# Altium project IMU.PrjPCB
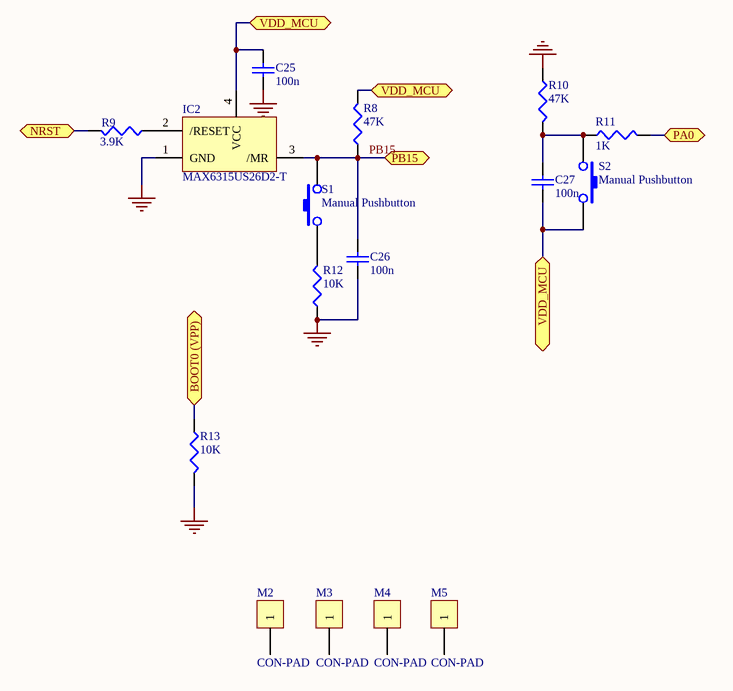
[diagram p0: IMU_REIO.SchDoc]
4 sheets, 58 parts. Net scope: flat (ports and power ports of the same name join across sheets).
Board file: IMU(G).PcbDoc
Sheets:
  IMU_REIO.SchDoc
  IMU_Blue.SchDoc
  CPU_STM32F4.SchDoc
  IMU_POW.SchDoc

## Sheet IMU_REIO.SchDoc
size A4

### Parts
C25  100n  [0603]
C26  100n  [0603]
C27  100n  [0603]
IC2  MAX6315US26D2-T  [TO-253]
M2  CON-PAD  [BAD_MARK]
M3  CON-PAD  [BAD_MARK]
M4  CON-PAD  [BAD_MARK]
M5  CON-PAD  [BAD_MARK]
R8  47K  [0603]
R9  3.9K  [0603]
R10  47K  [0603]
R11  1K  [0603]
R12  10K  [0603]
R13  10K  [0603]
S1  Manual Pushbutton  [KEY-6*4]
S2  Manual Pushbutton  [KEY-6*4]

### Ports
BOOT0 (VPP), NRST, PA0, PB15, VDD_MCU

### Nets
GND: C25.2 C26.2 IC2.1(GND) R10.1 R12.1 R13.2
VBAT: C25.1 C27.2 IC2.4(VCC) R8.2 S2.2 ; port VDD_MCU
BOOT0 (VPP): R13.1 ; port BOOT0 (VPP)
NRST: R9.2 ; port NRST
PA0: R11.2 ; port PA0
PB15: C26.1 IC2.3(/MR) R8.1 S1.2 ; port PB15
NetC27_1: C27.1 R10.2 R11.1 S2.1
NetIC2_2: IC2.2(/RESET) R9.1
NetR12_2: R12.2 S1.1

Not connected (* = marked no-connect by the designer): M2 1; M3 1; M4 1; M5 1

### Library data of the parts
C25-C27 = Cap: TANTAMOUNT? 595D Vishay Sprague,50V,22.5mOhm
IC2 = MAX 6468: MAX 6468XS16D3 Reset and Supervisory Circuit
R8-R13 = Res3: Resistor
S1 S2 = 微动开关

## Sheet IMU_Blue.SchDoc
size A3
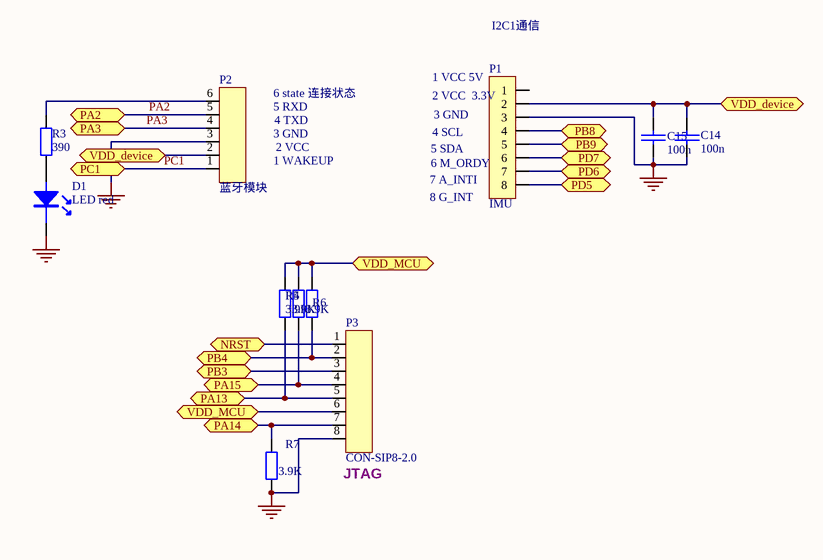
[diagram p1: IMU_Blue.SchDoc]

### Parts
C14  100n  [0603]
C15  100n  [0603]
D1  LED red  [D0805]
P1  IMU  [GY-85]
P2  蓝牙模块  [HC-06(35.7*15.2MM)]
P3  CON-SIP8-2.0  [PLUG1.27-8P]
R3  390  [0603]
R4  3.9K  [0603]
R5  3.9K  [0603]
R6  3.9K  [0603]
R7  3.9K  [0603]

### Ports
NRST, PA2, PA3, PA13, PA14, PA15, PB3, PB4, PB8, PB9, PC1, PD5, PD6, PD7, VDD_device, VDD_MCU

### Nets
GND: C14.1 C15.1 D1.K P1.3 P2.3 P3.8 R7.1
VBAT: P3.6 R4.2 R5.2 R6.2 ; port VDD_MCU
VDD_device: C14.2 C15.2 P1.2 P2.2 ; port VDD_device
NRST: P3.1 ; port NRST
PA2: P2.5 ; port PA2
PA3: P2.4 ; port PA3
PA13: P3.5 R4.1 ; port PA13
PA14: P3.7 R7.2 ; port PA14
PA15: P3.4 R5.1 ; port PA15
PB3: P3.3 ; port PB3
PB4: P3.2 R6.1 ; port PB4
PB8: P1.4 ; port PB8
PB9: P1.5 ; port PB9
PC1: P2.1 ; port PC1
PD5: P1.8 ; port PD5
PD6: P1.7 ; port PD6
PD7: P1.6 ; port PD7
NetD1_A: D1.A R3.1
NetP2_6: P2.6 R3.2

Not connected (* = marked no-connect by the designer): P1 1

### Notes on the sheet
- I2C1通信
- 6 state 连接状态
- 5 RXD
- 3 GND
- 4 TXD
- (near P1) 4 SCL
- (near P1) 1 VCC 5V
- (near P1) 2 VCC  3.3V
- (near P1) 3 GND
- 1 WAKEUP
- 2 VCC
- (near P1) 7 A_INTI
- (near P1) 8 G_INT
- (near P1) 6 M_ORDY
- 5 SDA
- (near P3) JTAG

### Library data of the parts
C14 C15 = C-SMD
D1 = diode-LED: LED
P1 = CON8-2.54: (栅)围栏式立(卧)8PIN
P2 = CON-SIP6-2.54: 单排针6PIN
P3 = CON-SIP8-2.0: 单排针8PIN
R3 = R-0603: 0603(SMD); 功率: 1/10w
R4-R7 = R-0805: 0805(SMD); 功率: 1/8w

## Sheet CPU_STM32F4.SchDoc
size A2
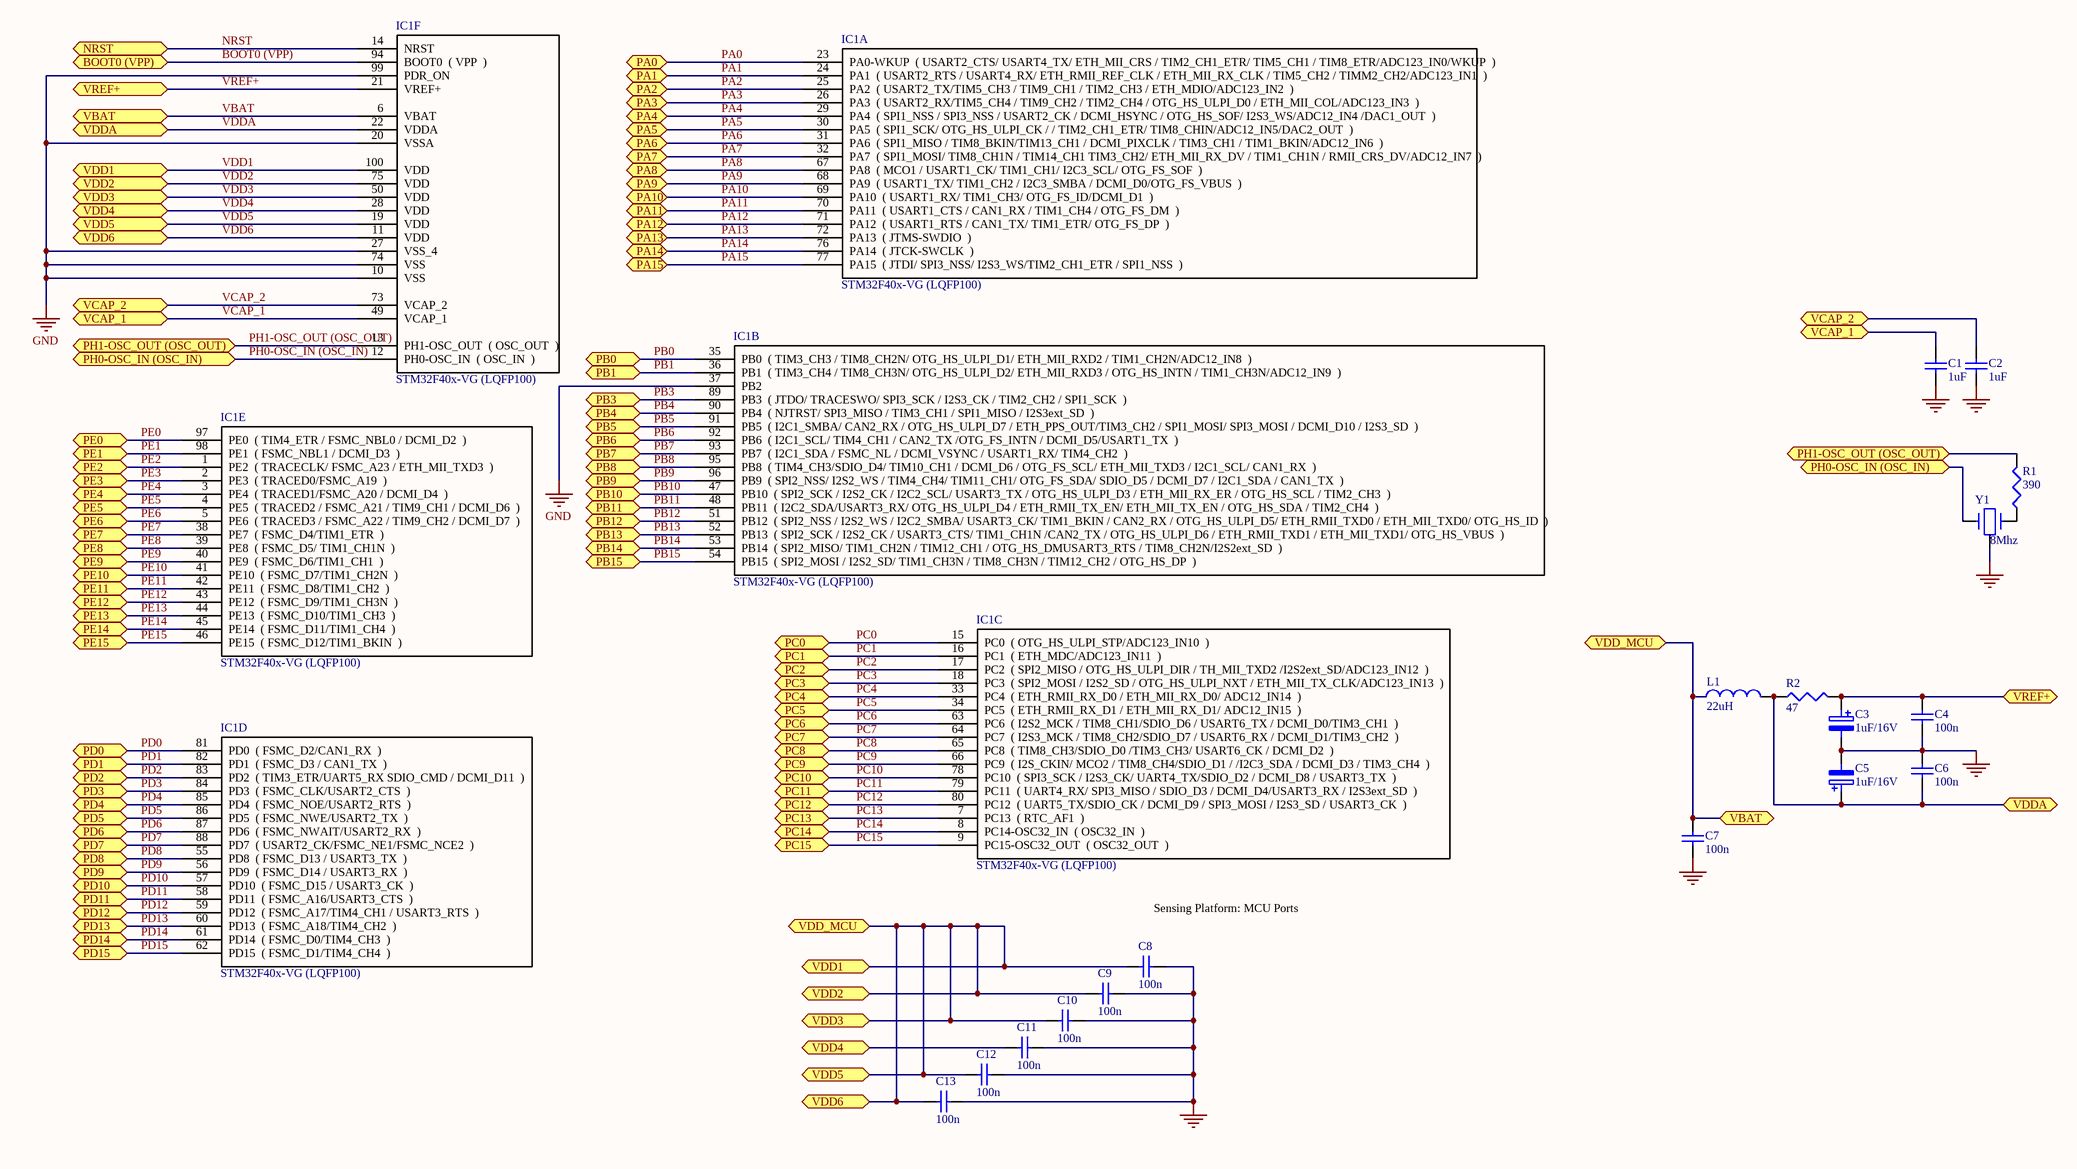
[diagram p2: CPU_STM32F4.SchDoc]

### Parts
C1  1uF  [0603]
C2  1uF  [0603]
C3  1uF/16V  [C-0805]
C4  100n  [0603]
C5  1uF/16V  [C-0805]
C6  100n  [0603]
C7  100n  [0603]
C8  100n  [0603]
C9  100n  [0603]
C10  100n  [0603]
C11  100n  [0603]
C12  100n  [0603]
C13  100n  [0603]
IC1  STM32F40x-VG (LQFP100)  [LQFP100 (14*14)]  (parts A,B,C,D,E,F of 6)
L1  22uH  [0603]
R1  390  [0603]
R2  47  [0603]
Y1  8Mhz  [XT-3.2*1.5]

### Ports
BOOT0 (VPP), NRST, PA0, PA1, PA2, PA3, PA4, PA5, PA6, PA7, PA8, PA9, PA10, PA11, PA12, PA13, PA14, PA15, PB0, PB1, PB3, PB4, PB5, PB6, PB7, PB8, PB9, PB10, PB11, PB12, PB13, PB14, PB15, PC0, PC1, PC2, PC3, PC4, PC5, PC6, PC7, PC8, PC9, PC10, PC11, PC12, PC13, PC14, PC15, PD0, PD1, PD2, PD3, PD4, PD5, PD6, PD7, PD8, PD9, PD10, PD11, PD12, PD13, PD14, PD15, PE0, PE1, PE2, PE3, PE4, PE5, PE6, PE7, PE8, PE9, PE10, PE11, PE12, PE13, PE14, PE15, PH0-OSC_IN (OSC_IN), PH1-OSC_OUT (OSC_OUT), VBAT, VCAP_1, VCAP_2, VDD1, VDD2, VDD3, VDD4, VDD5, VDD6, VDD_MCU, VDDA, VREF+

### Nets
GND: C1.1 C2.1 C3.2 C4.1 C5.2 C6.2 C7.1 C8.2 C9.2 C10.2 C11.2 C12.2 C13.2 IC1.10(VSS) IC1.20(VSSA) IC1.27(VSS_4) IC1.37(PB2) IC1.74(VSS) IC1.99(PDR_ON) Y1.2
VBAT: C7.2 C8.1 C9.1 C10.1 C12.1 C13.1 IC1.6(VBAT) IC1.11(VDD) IC1.19(VDD) IC1.50(VDD) IC1.75(VDD) IC1.100(VDD) L1.1 ; port VBAT, port VDD1, port VDD2, port VDD3, port VDD5, port VDD6, port VDD_MCU  [also labelled VDD1, VDD2, VDD3, VDD5, VDD6]
BOOT0 (VPP): IC1.94(BOOT0__(_VPP__)) ; port BOOT0 (VPP)
NRST: IC1.14(NRST) ; port NRST
PA0: IC1.23(PA0-WKUP__(_USART2_CTS/_USART4_TX/_ETH_MII_CRS_/_TIM2_CH1_ETR/_TIM5_CH1_/_TIM8_ETR/ADC123_IN0/WKUP__)) ; port PA0
PA1: IC1.24(PA1__(_USART2_RTS_/_USART4_RX/_ETH_RMII_REF_CLK_/_ETH_MII_RX_CLK_/_TIM5_CH2_/_TIMM2_CH2/ADC123_IN1__)) ; port PA1
PA2: IC1.25(PA2__(_USART2_TX/TIM5_CH3_/_TIM9_CH1_/_TIM2_CH3_/_ETH_MDIO/ADC123_IN2__)) ; port PA2
PA3: IC1.26(PA3__(_USART2_RX/TIM5_CH4_/_TIM9_CH2_/_TIM2_CH4_/_OTG_HS_ULPI_D0_/_ETH_MII_COL/ADC123_IN3__)) ; port PA3
PA4: IC1.29(PA4__(_SPI1_NSS_/_SPI3_NSS_/_USART2_CK_/_DCMI_HSYNC_/_OTG_HS_SOF/_I2S3_WS/ADC12_IN4_/DAC1_OUT__)) ; port PA4
PA5: IC1.30(PA5__(_SPI1_SCK/_OTG_HS_ULPI_CK_/_/_TIM2_CH1_ETR/_TIM8_CHIN/ADC12_IN5/DAC2_OUT__)) ; port PA5
PA6: IC1.31(PA6__(_SPI1_MISO_/_TIM8_BKIN/TIM13_CH1_/_DCMI_PIXCLK_/_TIM3_CH1_/_TIM1_BKIN/ADC12_IN6__)) ; port PA6
PA7: IC1.32(PA7__(_SPI1_MOSI/_TIM8_CH1N_/_TIM14_CH1_TIM3_CH2/_ETH_MII_RX_DV_/_TIM1_CH1N_/_RMII_CRS_DV/ADC12_IN7__)) ; port PA7
PA8: IC1.67(PA8__(_MCO1_/_USART1_CK/_TIM1_CH1/_I2C3_SCL/_OTG_FS_SOF__)) ; port PA8
PA9: IC1.68(PA9__(_USART1_TX/_TIM1_CH2_/_I2C3_SMBA_/_DCMI_D0/OTG_FS_VBUS__)) ; port PA9
PA10: IC1.69(PA10__(_USART1_RX/_TIM1_CH3/_OTG_FS_ID/DCMI_D1__)) ; port PA10
PA11: IC1.70(PA11__(_USART1_CTS_/_CAN1_RX_/_TIM1_CH4_/_OTG_FS_DM__)) ; port PA11
PA12: IC1.71(PA12__(_USART1_RTS_/_CAN1_TX/_TIM1_ETR/_OTG_FS_DP__)) ; port PA12
PA13: IC1.72(PA13__(_JTMS-SWDIO__)) ; port PA13
PA14: IC1.76(PA14__(_JTCK-SWCLK__)) ; port PA14
PA15: IC1.77(PA15__(_JTDI/_SPI3_NSS/_I2S3_WS/TIM2_CH1_ETR_/_SPI1_NSS__)) ; port PA15
PB0: IC1.35(PB0__(_TIM3_CH3_/_TIM8_CH2N/_OTG_HS_ULPI_D1/_ETH_MII_RXD2_/_TIM1_CH2N/ADC12_IN8__)) ; port PB0
PB1: IC1.36(PB1__(_TIM3_CH4_/_TIM8_CH3N/_OTG_HS_ULPI_D2/_ETH_MII_RXD3_/_OTG_HS_INTN_/_TIM1_CH3N/ADC12_IN9__)) ; port PB1
PB3: IC1.89(PB3__(_JTDO/_TRACESWO/_SPI3_SCK_/_I2S3_CK_/_TIM2_CH2_/_SPI1_SCK__)) ; port PB3
PB4: IC1.90(PB4__(_NJTRST/_SPI3_MISO_/_TIM3_CH1_/_SPI1_MISO_/_I2S3ext_SD__)) ; port PB4
PB5: IC1.91(PB5__(_I2C1_SMBA/_CAN2_RX_/_OTG_HS_ULPI_D7_/_ETH_PPS_OUT/TIM3_CH2_/_SPI1_MOSI/_SPI3_MOSI_/_DCMI_D10_/_I2S3_SD__)) ; port PB5
PB6: IC1.92(PB6__(_I2C1_SCL/_TIM4_CH1_/_CAN2_TX_/OTG_FS_INTN_/_DCMI_D5/USART1_TX__)) ; port PB6
PB7: IC1.93(PB7__(_I2C1_SDA_/_FSMC_NL_/_DCMI_VSYNC_/_USART1_RX/_TIM4_CH2__)) ; port PB7
PB8: IC1.95(PB8__(_TIM4_CH3/SDIO_D4/_TIM10_CH1_/_DCMI_D6_/_OTG_FS_SCL/_ETH_MII_TXD3_/_I2C1_SCL/_CAN1_RX__)) ; port PB8
PB9: IC1.96(PB9__(_SPI2_NSS/_I2S2_WS_/_TIM4_CH4/_TIM11_CH1/_OTG_FS_SDA/_SDIO_D5_/_DCMI_D7_/_I2C1_SDA_/_CAN1_TX__)) ; port PB9
PB10: IC1.47(PB10__(_SPI2_SCK_/_I2S2_CK_/_I2C2_SCL/_USART3_TX_/_OTG_HS_ULPI_D3_/_ETH_MII_RX_ER_/_OTG_HS_SCL_/_TIM2_CH3__)) ; port PB10
PB11: IC1.48(PB11__(_I2C2_SDA/USART3_RX/_OTG_HS_ULPI_D4_/_ETH_RMII_TX_EN/_ETH_MII_TX_EN_/_OTG_HS_SDA_/_TIM2_CH4__)) ; port PB11
PB12: IC1.51(PB12__(_SPI2_NSS_/_I2S2_WS_/_I2C2_SMBA/_USART3_CK/_TIM1_BKIN_/_CAN2_RX_/_OTG_HS_ULPI_D5/_ETH_RMII_TXD0_/_ETH_MII_TXD0/_OTG_HS_ID__)) ; port PB12
PB13: IC1.52(PB13__(_SPI2_SCK_/_I2S2_CK_/_USART3_CTS/_TIM1_CH1N_/CAN2_TX_/_OTG_HS_ULPI_D6_/_ETH_RMII_TXD1_/_ETH_MII_TXD1/_OTG_HS_VBUS__)) ; port PB13
PB14: IC1.53(PB14__(_SPI2_MISO/_TIM1_CH2N_/_TIM12_CH1_/_OTG_HS_DMUSART3_RTS_/_TIM8_CH2N/I2S2ext_SD__)) ; port PB14
PB15: IC1.54(PB15__(_SPI2_MOSI_/_I2S2_SD/_TIM1_CH3N_/_TIM8_CH3N_/_TIM12_CH2_/_OTG_HS_DP__)) ; port PB15
PC0: IC1.15(PC0__(_OTG_HS_ULPI_STP/ADC123_IN10__)) ; port PC0
PC1: IC1.16(PC1__(_ETH_MDC/ADC123_IN11__)) ; port PC1
PC2: IC1.17(PC2__(_SPI2_MISO_/_OTG_HS_ULPI_DIR_/_TH_MII_TXD2_/I2S2ext_SD/ADC123_IN12__)) ; port PC2
PC3: IC1.18(PC3__(_SPI2_MOSI_/_I2S2_SD_/_OTG_HS_ULPI_NXT_/_ETH_MII_TX_CLK/ADC123_IN13__)) ; port PC3
PC4: IC1.33(PC4__(_ETH_RMII_RX_D0_/_ETH_MII_RX_D0/_ADC12_IN14__)) ; port PC4
PC5: IC1.34(PC5__(_ETH_RMII_RX_D1_/_ETH_MII_RX_D1/_ADC12_IN15__)) ; port PC5
PC6: IC1.63(PC6__(_I2S2_MCK_/_TIM8_CH1/SDIO_D6_/_USART6_TX_/_DCMI_D0/TIM3_CH1__)) ; port PC6
PC7: IC1.64(PC7__(_I2S3_MCK_/_TIM8_CH2/SDIO_D7_/_USART6_RX_/_DCMI_D1/TIM3_CH2__)) ; port PC7
PC8: IC1.65(PC8__(_TIM8_CH3/SDIO_D0_/TIM3_CH3/_USART6_CK_/_DCMI_D2__)) ; port PC8
PC9: IC1.66(PC9__(_I2S_CKIN/_MCO2_/_TIM8_CH4/SDIO_D1_/_/I2C3_SDA_/_DCMI_D3_/_TIM3_CH4__)) ; port PC9
PC10: IC1.78(PC10__(_SPI3_SCK_/_I2S3_CK/_UART4_TX/SDIO_D2_/_DCMI_D8_/_USART3_TX__)) ; port PC10
PC11: IC1.79(PC11__(_UART4_RX/_SPI3_MISO_/_SDIO_D3_/_DCMI_D4/USART3_RX_/_I2S3ext_SD__)) ; port PC11
PC12: IC1.80(PC12__(_UART5_TX/SDIO_CK_/_DCMI_D9_/_SPI3_MOSI_/_I2S3_SD_/_USART3_CK__)) ; port PC12
PC13: IC1.7(PC13__(_RTC_AF1__)) ; port PC13
PC14: IC1.8(PC14-OSC32_IN__(_OSC32_IN__)) ; port PC14
PC15: IC1.9(PC15-OSC32_OUT__(_OSC32_OUT__)) ; port PC15
PD0: IC1.81(PD0__(_FSMC_D2/CAN1_RX__)) ; port PD0
PD1: IC1.82(PD1__(_FSMC_D3_/_CAN1_TX__)) ; port PD1
PD2: IC1.83(PD2__(_TIM3_ETR/UART5_RX_SDIO_CMD_/_DCMI_D11__)) ; port PD2
PD3: IC1.84(PD3__(_FSMC_CLK/USART2_CTS__)) ; port PD3
PD4: IC1.85(PD4__(_FSMC_NOE/USART2_RTS__)) ; port PD4
PD5: IC1.86(PD5__(_FSMC_NWE/USART2_TX__)) ; port PD5
PD6: IC1.87(PD6__(_FSMC_NWAIT/USART2_RX__)) ; port PD6
PD7: IC1.88(PD7__(_USART2_CK/FSMC_NE1/FSMC_NCE2__)) ; port PD7
PD8: IC1.55(PD8__(_FSMC_D13_/_USART3_TX__)) ; port PD8
PD9: IC1.56(PD9__(_FSMC_D14_/_USART3_RX__)) ; port PD9
PD10: IC1.57(PD10__(_FSMC_D15_/_USART3_CK__)) ; port PD10
PD11: IC1.58(PD11__(_FSMC_A16/USART3_CTS__)) ; port PD11
PD12: IC1.59(PD12__(_FSMC_A17/TIM4_CH1_/_USART3_RTS__)) ; port PD12
PD13: IC1.60(PD13__(_FSMC_A18/TIM4_CH2__)) ; port PD13
PD14: IC1.61(PD14__(_FSMC_D0/TIM4_CH3__)) ; port PD14
PD15: IC1.62(PD15__(_FSMC_D1/TIM4_CH4__)) ; port PD15
PE0: IC1.97(PE0__(_TIM4_ETR_/_FSMC_NBL0_/_DCMI_D2__)) ; port PE0
PE1: IC1.98(PE1__(_FSMC_NBL1_/_DCMI_D3__)) ; port PE1
PE2: IC1.1(PE2__(_TRACECLK/_FSMC_A23_/_ETH_MII_TXD3__)) ; port PE2
PE3: IC1.2(PE3__(_TRACED0/FSMC_A19__)) ; port PE3
PE4: IC1.3(PE4__(_TRACED1/FSMC_A20_/_DCMI_D4__)) ; port PE4
PE5: IC1.4(PE5__(_TRACED2_/_FSMC_A21_/_TIM9_CH1_/_DCMI_D6__)) ; port PE5
PE6: IC1.5(PE6__(_TRACED3_/_FSMC_A22_/_TIM9_CH2_/_DCMI_D7__)) ; port PE6
PE7: IC1.38(PE7__(_FSMC_D4/TIM1_ETR__)) ; port PE7
PE8: IC1.39(PE8__(_FSMC_D5/_TIM1_CH1N__)) ; port PE8
PE9: IC1.40(PE9__(_FSMC_D6/TIM1_CH1__)) ; port PE9
PE10: IC1.41(PE10__(_FSMC_D7/TIM1_CH2N__)) ; port PE10
PE11: IC1.42(PE11__(_FSMC_D8/TIM1_CH2__)) ; port PE11
PE12: IC1.43(PE12__(_FSMC_D9/TIM1_CH3N__)) ; port PE12
PE13: IC1.44(PE13__(_FSMC_D10/TIM1_CH3__)) ; port PE13
PE14: IC1.45(PE14__(_FSMC_D11/TIM1_CH4__)) ; port PE14
PE15: IC1.46(PE15__(_FSMC_D12/TIM1_BKIN__)) ; port PE15
PH0-OSC_IN (OSC_IN): IC1.12(PH0-OSC_IN__(_OSC_IN__)) Y1.1 ; port PH0-OSC_IN (OSC_IN)
PH1-OSC_OUT (OSC_OUT): IC1.13(PH1-OSC_OUT__(_OSC_OUT__)) R1.2 ; port PH1-OSC_OUT (OSC_OUT)
VCAP_1: C1.2 IC1.49(VCAP_1) ; port VCAP_1
VCAP_2: C2.2 IC1.73(VCAP_2) ; port VCAP_2
VDD4: C11.1 IC1.28(VDD) ; port VDD4
VDDA: C5.1 C6.1 IC1.22(VDDA) L1.2 R2.1 ; port VDDA
VREF+: C3.1 C4.2 IC1.21(VREF+) R2.2 ; port VREF+
NetR1_1: R1.1 Y1.3

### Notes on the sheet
- (near C8) Sensing Platform: MCU Ports

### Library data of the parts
C1 C2 = Cap: TANTAMOUNT? 595D Vishay Sprague,50V,22.5mOhm; Value: 1u
C3 C5 = C-A(3216-18): 耐压: 10V
C4 C6 C7 C9-C13 = Cap: as C25 on sheet IMU_REIO
C8 = Cap: TANTAMOUNT? 595D Vishay Sprague,50V,22.5mOhm; Value: 4.7u
IC1 = STM32F40x-VG
L1 = Inductor: fcm1608-0603; Code_IEC: 1005
R1 R2 = Res3: Resistor
Y1 = CRYSTAL-X3: 3PIN; 频率: 20MHZ-39.9MHZ

## Sheet IMU_POW.SchDoc
size A3
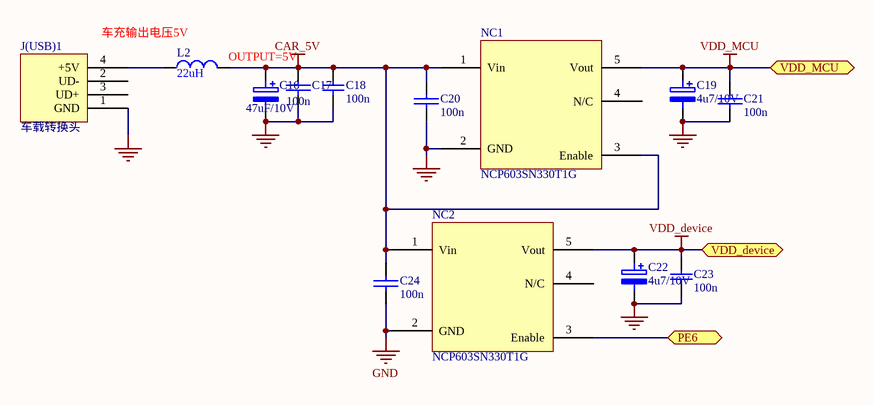
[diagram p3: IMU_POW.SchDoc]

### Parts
C16  47uF/10V  [C-A(3216-18)]
C17  100n  [0603]
C18  100n  [0603]
C19  4u7/10V  [C-0805]
C20  100n  [0603]
C21  100n  [0603]
C22  4u7/10V  [C-0805]
C23  100n  [0603]
C24  100n  [0603]
J(USB)1  车载转换头  [USB-SMT]
L2  22uH  [0603]
NC1  NCP603SN330T1G  [TSSOP-5]
NC2  NCP603SN330T1G  [TSSOP-5]

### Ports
PE6, VDD_device, VDD_MCU

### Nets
CAR_5V: C16.1 C17.2 C18.2 C20.2 C24.2 L2.2 NC1.1(Vin) NC1.3(Enable) NC2.1(Vin)
GND: C16.2 C17.1 C18.1 C19.2 C20.1 C21.1 C22.2 C23.1 C24.1 J(USB)1.1(GND) NC1.2(GND) NC2.2(GND)
VDD_device: C22.1 C23.2 NC2.5(Vout) ; port VDD_device
VDD_MCU: C19.1 C21.2 NC1.5(Vout) ; port VDD_MCU  [project net VBAT]
PE6: NC2.3(Enable) ; port PE6
NetJ(USB)1_4: J(USB)1.4(+5V) L2.1

Not connected (* = marked no-connect by the designer): J(USB)1 2(UD-) 3(UD+); NC1 4(N/C); NC2 4(N/C)

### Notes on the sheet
- 车充输出电压5V
- OUTPUT=5V

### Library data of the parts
C16 C19 C22 = C-A(3216-18): 耐压: 10V
C17 = C-SMD电容
C18 = Cap: as C25 on sheet IMU_REIO
C20 = C
C21 C24 = C-SMD
C23 = Cap Semi: Capacitor (Semiconductor SIM Model); Value: 100nF
J(USB)1 = CON-USB1: USB
L2 = INDUCTOR
NC1 NC2 = NCP551

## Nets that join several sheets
GND: IMU_REIO (6 pins), IMU_Blue (7 pins), CPU_STM32F4 (20 pins), IMU_POW (12 pins)
VBAT: IMU_REIO (5 pins), IMU_Blue (P3.6 R4.2 R5.2 R6.2), CPU_STM32F4 (13 pins), IMU_POW (C19.1 C21.2 NC1.5)
VDD_device: IMU_Blue (C14.2 C15.2 P1.2 P2.2), IMU_POW (C22.1 C23.2 NC2.5)
BOOT0 (VPP): IMU_REIO (R13.1), CPU_STM32F4 (IC1.94)
NRST: IMU_REIO (R9.2), IMU_Blue (P3.1), CPU_STM32F4 (IC1.14)
PA0: IMU_REIO (R11.2), CPU_STM32F4 (IC1.23)
PA2: IMU_Blue (P2.5), CPU_STM32F4 (IC1.25)
PA3: IMU_Blue (P2.4), CPU_STM32F4 (IC1.26)
PA13: IMU_Blue (P3.5 R4.1), CPU_STM32F4 (IC1.72)
PA14: IMU_Blue (P3.7 R7.2), CPU_STM32F4 (IC1.76)
PA15: IMU_Blue (P3.4 R5.1), CPU_STM32F4 (IC1.77)
PB3: IMU_Blue (P3.3), CPU_STM32F4 (IC1.89)
PB4: IMU_Blue (P3.2 R6.1), CPU_STM32F4 (IC1.90)
PB8: IMU_Blue (P1.4), CPU_STM32F4 (IC1.95)
PB9: IMU_Blue (P1.5), CPU_STM32F4 (IC1.96)
PB15: IMU_REIO (C26.1 IC2.3 R8.1 S1.2), CPU_STM32F4 (IC1.54)
PC1: IMU_Blue (P2.1), CPU_STM32F4 (IC1.16)
PD5: IMU_Blue (P1.8), CPU_STM32F4 (IC1.86)
PD6: IMU_Blue (P1.7), CPU_STM32F4 (IC1.87)
PD7: IMU_Blue (P1.6), CPU_STM32F4 (IC1.88)
PE6: CPU_STM32F4 (IC1.5), IMU_POW (NC2.3)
